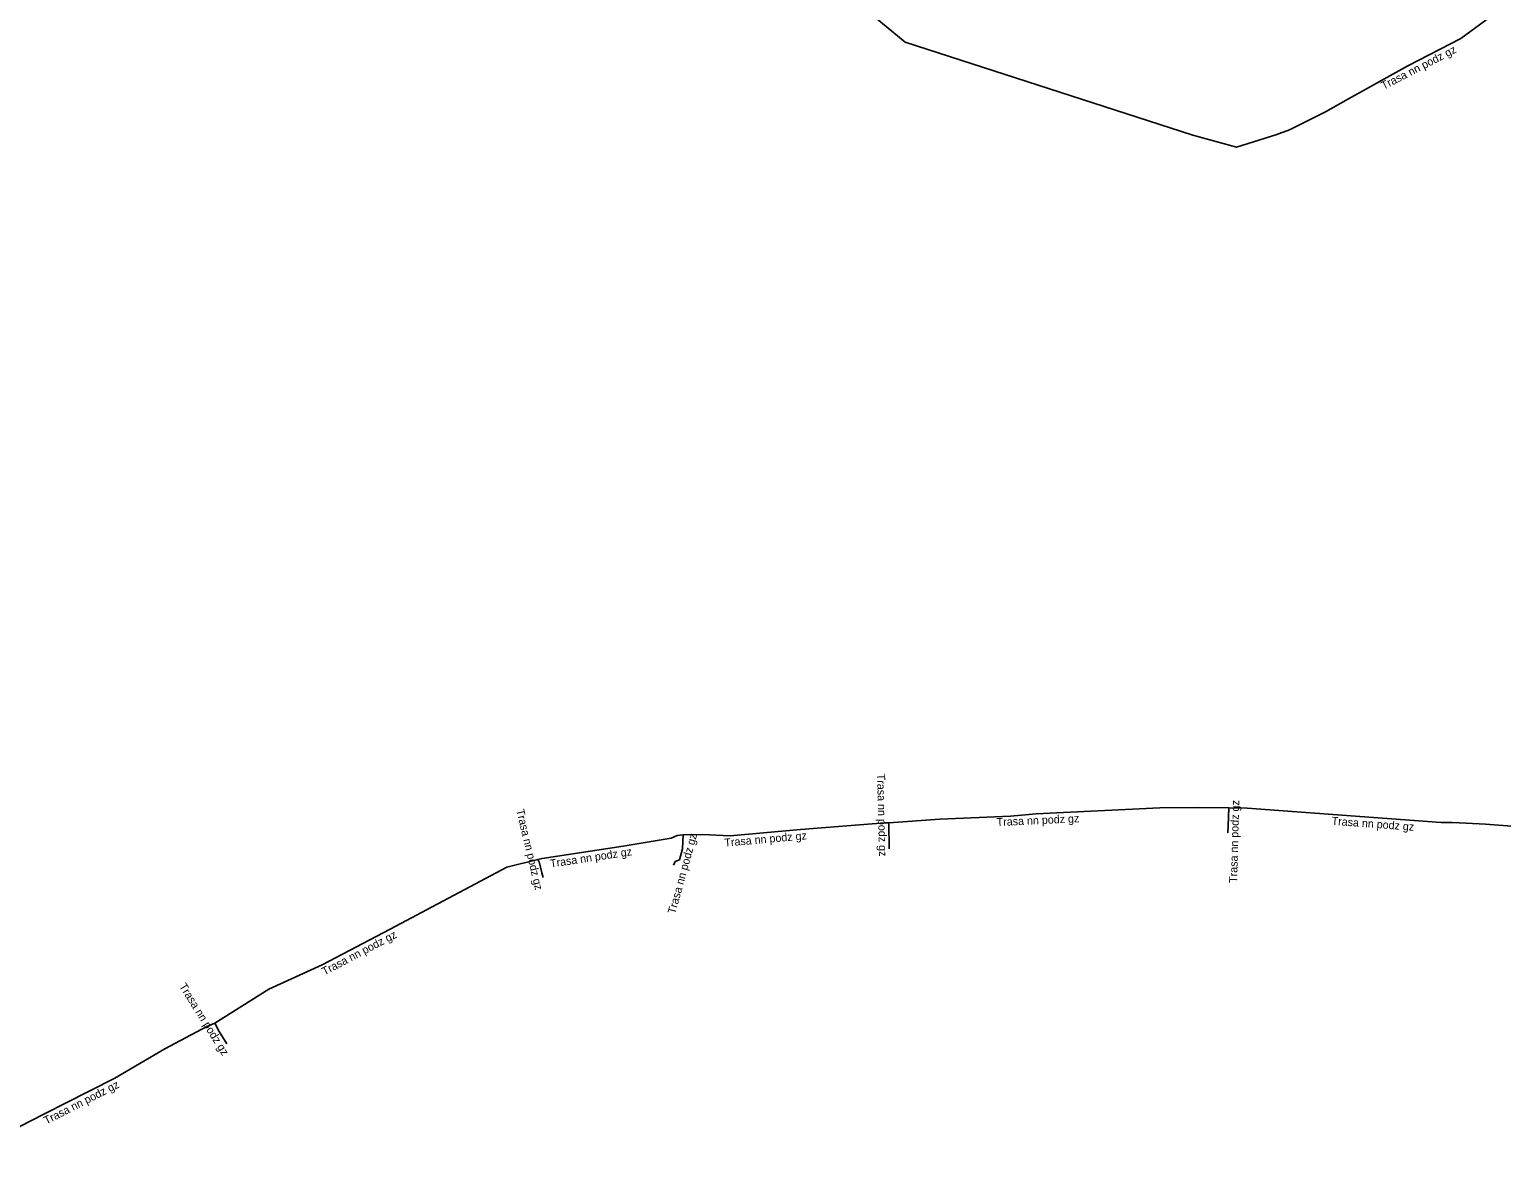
# Model space of a CAD drawing. Extents: x -687924 to -686708, y -1056742 to -1056249.
# Drawn here: x -687381 to -687289.1, y -1056484.2 to -1056414.3 of the extents above; entities that cross this region are included whole.
import ezdxf

# ---------------------------------------------------------------- set-up
doc = ezdxf.new("R2010")
doc.units = 0
doc.layers.add('Popiskový text - Ostatní atributy Trasy', color=7, linetype='Continuous')
doc.layers.add('Spojnice NN', color=7, linetype='Continuous')

msp = doc.modelspace()

# ---------------------------------------------------------------- linework, layer by layer
at = {"layer": 'Spojnice NN'}
for points in [[(-687303.16, -1056420.84), (-687305.62, -1056421.61), (-687308.33, -1056420.87), (-687326.31, -1056415.06), (-687340.65, -1056403.22), (-687358.94, -1056382.8), (-687372.31, -1056390.82), (-687377.1, -1056394.13)], [(-687284.61, -1056416.29), (-687285.5, -1056415.14), (-687287.06, -1056413.17), (-687287.89, -1056412.63), (-687289.09, -1056412.99), (-687291.59, -1056414.83), (-687294.9, -1056416.53), (-687298.62, -1056418.6), (-687300.06, -1056419.41), (-687302.29, -1056420.54), (-687303.16, -1056420.84)], [(-687306.1, -1056462.89), (-687307.92, -1056462.88), (-687310.39, -1056462.9), (-687318.13, -1056463.27), (-687319.74, -1056463.42), (-687324.15, -1056463.61), (-687327.34, -1056463.83)], [(-687306.1, -1056462.89), (-687306.13, -1056464.02), (-687306.15, -1056464.46)], [(-687286.25, -1056465.28), (-687286.27, -1056464.47), (-687287.04, -1056464.14), (-687290.05, -1056463.91), (-687291.26, -1056463.85), (-687292.13, -1056463.81), (-687292.82, -1056463.8), (-687304.95, -1056462.91), (-687306.1, -1056462.89)], [(-687327.34, -1056463.83), (-687327.58, -1056463.83), (-687332.84, -1056464.24), (-687337.24, -1056464.64), (-687338.97, -1056464.56), (-687340.19, -1056464.57)], [(-687327.34, -1056463.83), (-687327.3, -1056465.45)], [(-687340.19, -1056464.57), (-687340.56, -1056464.63), (-687340.92, -1056464.78), (-687343.92, -1056465.28), (-687348.99, -1056466.05), (-687349.25, -1056466.11)], [(-687340.19, -1056464.57), (-687340.22, -1056465.45), (-687340.41, -1056466.14), (-687340.67, -1056466.25), (-687340.78, -1056466.48)], [(-687349.25, -1056466.11), (-687351.2, -1056466.6), (-687358.49, -1056470.48), (-687362.73, -1056472.71), (-687366.07, -1056474.22), (-687369.43, -1056476.35)], [(-687349.25, -1056466.11), (-687349.16, -1056466.33), (-687349.01, -1056466.96), (-687348.93, -1056467.24)], [(-687369.43, -1056476.35), (-687369.93, -1056476.55), (-687372.56, -1056477.94), (-687375.68, -1056479.77), (-687378.76, -1056481.34), (-687381.05, -1056482.5), (-687383.17, -1056483.62), (-687384.21, -1056484.24)], [(-687369.43, -1056476.35), (-687369.16, -1056476.86), (-687368.68, -1056477.63)]]:
    msp.add_lwpolyline(points, dxfattribs=at)

# ---------------------------------------------------------------- texts
at = {"layer": 'Popiskový text - Ostatní atributy Trasy'}
for rotation, p in [(27.18481, (-687296.418, -1056418.04)), (271.41442, (-687328.066, -1056460.764)), (88.47923, (-687305.574, -1056467.585)), (283.3925, (-687350.613, -1056463.034)), (2.73686, (-687320.584, -1056464.038)), (355.80362, (-687299.68, -1056463.948)), (74.60445, (-687340.677, -1056469.556)), (5.19443, (-687337.582, -1056465.323)), (8.63573, (-687348.457, -1056466.627)), (27.74183, (-687362.592, -1056473.372)), (301.93845, (-687371.684, -1056474.04)), (27.00977, (-687379.968, -1056482.686))]:
    msp.add_text('Trasa nn podz gz', height=0.5, rotation=rotation, dxfattribs=at).set_placement(p)

doc.saveas('drawing.dxf')
